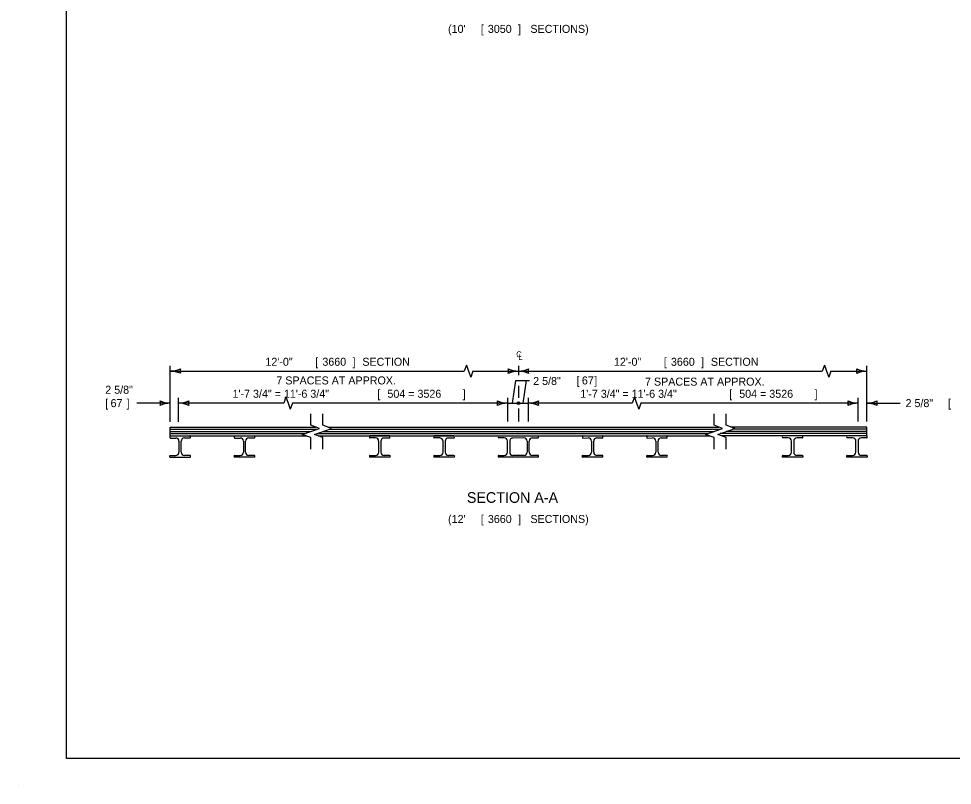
# Model space of a CAD drawing. Extents: x 49991.4 to 50021, y 49987.6 to 50011.4.
# Drawn here: x 49999.02 to 50006.02, y 49987.6 to 49993.35 of the extents above; entities that cross this region are included whole.
import ezdxf

# ---------------------------------------------------------------- set-up
doc = ezdxf.new("R2010")
doc.units = 0
for name, color, linetype in [('Level 1', 7, 'Continuous'), ('Level 10', 7, 'Continuous'), ('Level 2', 7, 'Continuous'), ('Level 3', 7, 'Continuous'), ('Level 6', 7, 'Continuous')]:
    doc.layers.add(name, color=color, linetype=linetype)

msp = doc.modelspace()

# ---------------------------------------------------------------- linework, layer by layer
at = {"layer": 'Level 1'}
for p, q in [((50000.1608, 49990.2845), (50001.2499, 49990.2846)), ((50000.1608, 49990.219), (50000.1608, 49990.2845)), ((50001.3411, 49990.2846), (50004.2726, 49990.2846)), ((50005.3818, 49990.2846), (50004.3638, 49990.2846)), ((50005.3818, 49990.219), (50005.3818, 49990.2846)), ((50000.1608, 49990.2682), (50001.2606, 49990.2682)), ((50000.1608, 49990.2518), (50001.2144, 49990.2518)), ((50000.1608, 49990.2355), (50001.1684, 49990.2355)), ((50000.1608, 49990.219), (50001.1789, 49990.219)), ((50000.1608, 49990.2184), (50000.3087, 49990.2186)), ((50000.6434, 49990.2184), (50000.7913, 49990.2186)), ((50001.2596, 49990.2355), (50004.1911, 49990.2355)), ((50001.2701, 49990.219), (50004.2016, 49990.219)), ((50001.3056, 49990.2518), (50004.2371, 49990.2518)), ((50001.3518, 49990.2682), (50004.2833, 49990.2682)), ((50001.8048, 49990.2183), (50001.657, 49990.2186)), ((50002.2874, 49990.2183), (50002.1396, 49990.2186)), ((50002.6221, 49990.2186), (50002.918, 49990.2187)), ((50003.2526, 49990.2185), (50003.4005, 49990.2187)), ((50003.7352, 49990.2185), (50003.8832, 49990.2187)), ((50005.3818, 49990.2355), (50004.2823, 49990.2355)), ((50005.3818, 49990.219), (50004.2928, 49990.219)), ((50005.3818, 49990.2518), (50004.3283, 49990.2518)), ((50005.3818, 49990.2682), (50004.3745, 49990.2682)), ((50004.8992, 49990.2186), (50004.7513, 49990.2188)), ((50005.3818, 49990.2186), (50005.2339, 49990.2188)), ((50000.1609, 49990.202), (50000.2015, 49990.2021)), ((50000.226, 49990.1776), (50000.226, 49990.096)), ((50000.2428, 49990.0962), (50000.2428, 49990.1777)), ((50000.2671, 49990.2022), (50000.3087, 49990.2023)), ((50000.6435, 49990.202), (50000.6841, 49990.2021)), ((50000.7086, 49990.1776), (50000.7086, 49990.096)), ((50000.7254, 49990.0962), (50000.7254, 49990.1777)), ((50000.7497, 49990.2022), (50000.7913, 49990.2023)), ((50001.6985, 49990.2022), (50001.6569, 49990.2022)), ((50001.7229, 49990.0962), (50001.7229, 49990.1777)), ((50001.7396, 49990.1776), (50001.7396, 49990.096)), ((50001.8048, 49990.202), (50001.7642, 49990.202)), ((50002.1811, 49990.2022), (50002.1396, 49990.2022)), ((50002.2055, 49990.0962), (50002.2055, 49990.1777)), ((50002.2222, 49990.1776), (50002.2222, 49990.096)), ((50002.2874, 49990.202), (50002.2468, 49990.202)), ((50002.6637, 49990.2022), (50002.6221, 49990.2022)), ((50002.6881, 49990.0962), (50002.6881, 49990.1777)), ((50002.7048, 49990.1776), (50002.7048, 49990.096)), ((50002.8107, 49990.2022), (50002.7294, 49990.202)), ((50002.8353, 49990.1777), (50002.8353, 49990.0961)), ((50002.852, 49990.0964), (50002.852, 49990.1778)), ((50002.8763, 49990.2023), (50002.918, 49990.2024)), ((50003.2527, 49990.2021), (50003.2933, 49990.2022)), ((50003.3178, 49990.1777), (50003.3178, 49990.0961)), ((50003.3346, 49990.0964), (50003.3346, 49990.1778)), ((50003.3589, 49990.2023), (50003.4005, 49990.2024)), ((50003.7353, 49990.2021), (50003.7759, 49990.2022)), ((50003.8004, 49990.1777), (50003.8004, 49990.0961)), ((50003.8172, 49990.0964), (50003.8172, 49990.1778)), ((50003.8415, 49990.2023), (50003.8832, 49990.2024)), ((50004.7929, 49990.2024), (50004.7513, 49990.2024)), ((50004.8172, 49990.0964), (50004.8172, 49990.1779)), ((50004.834, 49990.1778), (50004.834, 49990.0962)), ((50004.8992, 49990.2022), (50004.8586, 49990.2023)), ((50005.2755, 49990.2024), (50005.2339, 49990.2024)), ((50005.2998, 49990.0964), (50005.2998, 49990.1779)), ((50005.3166, 49990.1778), (50005.3166, 49990.0962)), ((50005.3818, 49990.2022), (50005.3412, 49990.2023)), ((50000.1612, 49990.0714), (50000.2016, 49990.0714)), ((50000.3087, 49990.0718), (50000.2674, 49990.0718)), ((50000.6438, 49990.0714), (50000.6842, 49990.0714)), ((50000.7913, 49990.0718), (50000.75, 49990.0718)), ((50001.6569, 49990.0718), (50001.6983, 49990.0718)), ((50001.8045, 49990.0713), (50001.7641, 49990.0714)), ((50002.1395, 49990.0718), (50002.1809, 49990.0718)), ((50002.2871, 49990.0713), (50002.2467, 49990.0714)), ((50002.6221, 49990.0718), (50002.6635, 49990.0718)), ((50002.8108, 49990.0716), (50002.7293, 49990.0714)), ((50002.918, 49990.0719), (50002.8766, 49990.0719)), ((50003.253, 49990.0715), (50003.2934, 49990.0716)), ((50003.4006, 49990.0719), (50003.3592, 49990.0719)), ((50003.7356, 49990.0715), (50003.776, 49990.0716)), ((50003.8832, 49990.0719), (50003.8418, 49990.0719)), ((50004.7513, 49990.072), (50004.7927, 49990.072)), ((50004.8989, 49990.0716), (50004.8584, 49990.0716)), ((50005.2339, 49990.072), (50005.2753, 49990.072)), ((50005.3815, 49990.0716), (50005.341, 49990.0716)), ((50000.1603, 49990.0576), (50000.3094, 49990.0576)), ((50000.792, 49990.0576), (50000.6429, 49990.0576)), ((50001.8055, 49990.0576), (50001.6562, 49990.0576)), ((50002.2881, 49990.0576), (50002.1388, 49990.0576)), ((50002.9185, 49990.0577), (50002.6213, 49990.0576)), ((50003.4011, 49990.0577), (50003.2523, 49990.0577)), ((50003.8838, 49990.0577), (50003.7348, 49990.0577)), ((50004.8999, 49990.0578), (50004.7506, 49990.0578)), ((50005.3828, 49990.0579), (50005.233, 49990.0579)), ((49999.0245, 49987.5988), (49999.0245, 49987.5988))]:
    msp.add_line(p, q, dxfattribs=at)
msp.add_lwpolyline([(49999.3835, 49998.9992), (50016.7501, 49998.9992), (50016.7501, 49987.7988), (49999.3835, 49987.7988)], close=True, dxfattribs=at)
for centre, radius, start, end in [((50001.7022, 49990.1815), 0.021, 349.58231, 100.06069), ((50000.2015, 49990.1776), 0.0245, 0.13085, 90.13085), ((50000.2676, 49990.1774), 0.0248, 91.12542, 179.23159), ((50000.6841, 49990.1776), 0.0245, 0.13085, 90.13085), ((50000.7475, 49990.1801), 0.0222, 84.14406, 186.21295), ((50001.7641, 49990.1775), 0.0245, 89.86915, 179.86915), ((50002.1778, 49990.1745), 0.0279, 6.54158, 83.10142), ((50002.2467, 49990.1775), 0.0245, 89.86915, 179.86915), ((50002.6657, 49990.1798), 0.0225, 354.61543, 95.02756), ((50002.7293, 49990.1775), 0.0245, 89.86915, 179.86915), ((50002.8108, 49990.1777), 0.0245, 0.13085, 90.13085), ((50002.874, 49990.1803), 0.0222, 83.95297, 186.40404), ((50003.2933, 49990.1777), 0.0245, 0.13085, 90.13085), ((50003.3583, 49990.1787), 0.0237, 88.32603, 182.03098), ((50003.7759, 49990.1777), 0.0245, 0.13085, 90.13085), ((50003.8403, 49990.1792), 0.0232, 87.00728, 183.34973), ((50004.7928, 49990.178), 0.0244, 359.87659, 89.76641), ((50004.8579, 49990.1784), 0.0239, 88.36941, 181.3689), ((50005.2767, 49990.1792), 0.0232, 356.71012, 92.93287), ((50005.3396, 49990.1793), 0.023, 86.11132, 183.62699), ((50000.2015, 49990.0959), 0.0245, 270.13085, 0.13085), ((50000.2673, 49990.0963), 0.0245, 180.13085, 270.13085), ((50000.6841, 49990.0959), 0.0245, 270.13085, 0.13085), ((50000.7499, 49990.0963), 0.0245, 180.13085, 270.13085), ((50001.6984, 49990.0963), 0.0245, 269.86915, 359.86915), ((50001.7641, 49990.0959), 0.0245, 179.86915, 269.86915), ((50002.181, 49990.0963), 0.0245, 269.86915, 359.86915), ((50002.2467, 49990.0959), 0.0245, 179.86915, 269.86915), ((50002.6636, 49990.0963), 0.0245, 269.86915, 359.86915), ((50002.7293, 49990.0959), 0.0245, 179.86915, 269.86915), ((50002.8108, 49990.0961), 0.0245, 270.13085, 0.13085), ((50002.8765, 49990.0964), 0.0245, 180.13085, 270.13085), ((50003.2933, 49990.0961), 0.0245, 270.13085, 0.13085), ((50003.3591, 49990.0964), 0.0245, 180.13085, 270.13085), ((50003.7759, 49990.0961), 0.0245, 270.13085, 0.13085), ((50003.8417, 49990.0964), 0.0245, 180.13085, 270.13085), ((50004.7927, 49990.0965), 0.0245, 269.86915, 359.86915), ((50004.8585, 49990.0961), 0.0245, 179.86915, 269.86915), ((50005.2753, 49990.0965), 0.0245, 269.86915, 359.86915), ((50005.3411, 49990.0961), 0.0245, 179.86915, 269.86915)]:
    msp.add_arc(centre, radius, start, end, dxfattribs=at)
for centre, major_axis, ratio, start_param, end_param in [((50000.1609, 49990.2102), (-0.00002, 0.00817), 0.356754, 0, 3.141593), ((50000.3087, 49990.2104), (0.00002, -0.00817), 0.392805, 0, 3.141593), ((50000.6435, 49990.2102), (-0.00002, 0.00817), 0.356754, 0, 3.141593), ((50000.7913, 49990.2104), (0.00002, -0.00817), 0.392805, 0, 3.141593), ((50001.657, 49990.2104), (-0.00002, -0.00817), 0.392805, 3.141593, 6.283185), ((50001.8048, 49990.2102), (0.00002, 0.00817), 0.356754, 3.141593, 6.283185), ((50002.1396, 49990.2104), (-0.00002, -0.00817), 0.392805, 3.141593, 6.283185), ((50002.2874, 49990.2102), (0.00002, 0.00817), 0.356754, 3.141593, 6.283185), ((50002.6222, 49990.2104), (-0.00002, -0.00817), 0.392805, 3.141593, 6.283185), ((50002.9179, 49990.2105), (0.00002, -0.00817), 0.392805, 0, 3.141593), ((50003.2527, 49990.2103), (-0.00002, 0.00817), 0.356754, 0, 3.141593), ((50003.4005, 49990.2105), (0.00002, -0.00817), 0.392805, 0, 3.141593), ((50003.7353, 49990.2103), (-0.00002, 0.00817), 0.356754, 0, 3.141593), ((50003.8831, 49990.2105), (0.00002, -0.00817), 0.392805, 0, 3.141593), ((50004.7513, 49990.2106), (-0.00002, -0.00817), 0.392805, 3.141593, 6.283185), ((50004.8992, 49990.2104), (0.00002, 0.00817), 0.356754, 3.141593, 6.283185), ((50005.2339, 49990.2106), (-0.00002, -0.00817), 0.392805, 3.141593, 6.283185), ((50005.3818, 49990.2104), (0.00002, 0.00817), 0.356754, 3.141593, 6.283185), ((50000.1614, 49990.0644), (-0.00025, 0.00695), 0.928868, 0, 2.919512), ((50000.3087, 49990.0646), (-0.00003, -0.00717), 0.534325, 0.187696, 3.141593), ((50000.644, 49990.0644), (-0.00025, 0.00695), 0.928868, 0, 2.919512), ((50000.7913, 49990.0646), (-0.00003, -0.00717), 0.534325, 0.187696, 3.141593), ((50001.657, 49990.0646), (0.00003, -0.00717), 0.534325, 3.141593, 6.076715), ((50001.8042, 49990.0644), (0.00025, 0.00695), 0.928868, 3.382741, 6.283185), ((50002.1396, 49990.0646), (0.00003, -0.00717), 0.534325, 3.141593, 6.076713), ((50002.2868, 49990.0644), (0.00025, 0.00695), 0.928868, 3.382741, 6.283185), ((50002.6222, 49990.0646), (0.00003, -0.00717), 0.534325, 3.141593, 6.043934), ((50002.9179, 49990.0647), (-0.00003, -0.00717), 0.534325, 0.146109, 3.141593), ((50003.2532, 49990.0645), (-0.00025, 0.00695), 0.928868, 0, 2.951883), ((50003.4005, 49990.0647), (-0.00003, -0.00717), 0.534325, 0.161043, 3.141593), ((50003.7358, 49990.0645), (-0.00025, 0.00695), 0.928868, 0, 2.93527), ((50003.8831, 49990.0647), (-0.00003, -0.00717), 0.534325, 0.176923, 3.141593), ((50004.7513, 49990.0648), (0.00003, -0.00717), 0.534325, 3.141593, 6.095489), ((50004.8986, 49990.0646), (0.00025, 0.00695), 0.928868, 3.382741, 6.283185), ((50005.2339, 49990.0648), (0.00003, -0.00717), 0.534325, 3.141593, 6.039934), ((50005.3812, 49990.0646), (0.00025, 0.00695), 0.928868, 3.435164, 6.283185)]:
    msp.add_ellipse(centre, major_axis=major_axis, ratio=ratio, start_param=start_param, end_param=end_param, dxfattribs=at)
at = {"layer": 'Level 10'}
msp.add_line((50002.7702, 49990.7434), (50002.7702, 49990.7434), dxfattribs=at)
at = {"layer": 'Level 3'}
for p, q in [((50000.1608, 49990.3245), (50000.1608, 49990.7437)), ((50000.1608, 49990.7037), (50001.9664, 49990.7034)), ((50001.9664, 49990.7034), (50002.364, 49990.7034)), ((50002.3802, 49990.749), (50002.364, 49990.7034)), ((50002.3802, 49990.749), (50002.3964, 49990.7034)), ((50002.3964, 49990.7034), (50002.4126, 49990.6576)), ((50002.4288, 49990.7034), (50002.4126, 49990.6576)), ((50002.4288, 49990.7034), (50002.7702, 49990.7034)), ((50002.7702, 49990.7434), (50002.7702, 49990.6734)), ((50002.7702, 49990.7034), (50004.5789, 49990.7031)), ((50004.5789, 49990.7031), (50005.0481, 49990.7031)), ((50005.0643, 49990.7487), (50005.0481, 49990.7031)), ((50005.0643, 49990.7487), (50005.0805, 49990.7031)), ((50005.0805, 49990.7031), (50005.0967, 49990.6573)), ((50005.1129, 49990.7031), (50005.0967, 49990.6573)), ((50005.1129, 49990.7031), (50005.3819, 49990.7031)), ((50005.3819, 49990.3246), (50005.3819, 49990.7431)), ((50002.7256, 49990.4636), (50002.7506, 49990.6334)), ((50002.7506, 49990.6334), (50002.8534, 49990.6334)), ((50002.807, 49990.4635), (50002.832, 49990.6334)), ((50002.7702, 49990.5934), (50002.7702, 49990.5035)), ((50000.2232, 49990.3245), (50000.2232, 49990.5037)), ((50001.0278, 49990.5095), (50001.0116, 49990.4637)), ((50001.0278, 49990.5095), (50001.044, 49990.4637)), ((50002.6886, 49990.5037), (50002.6886, 49990.3246)), ((50002.8442, 49990.5034), (50002.8442, 49990.3246)), ((50003.6403, 49990.5092), (50003.6241, 49990.4634)), ((50003.6403, 49990.5092), (50003.6565, 49990.4634)), ((50005.3171, 49990.3246), (50005.3171, 49990.5034)), ((50000.1608, 49990.4637), (49999.9106, 49990.4637)), ((50001.0116, 49990.4637), (50000.2232, 49990.4637)), ((50001.044, 49990.4637), (50001.0602, 49990.4181)), ((50001.0764, 49990.4637), (50001.0602, 49990.4181)), ((50002.6886, 49990.4637), (50001.0764, 49990.4637)), ((50002.6886, 49990.4637), (50002.8442, 49990.4634)), ((50002.7702, 49990.4235), (50002.7702, 49990.3246)), ((50003.6241, 49990.4634), (50002.8442, 49990.4634)), ((50003.6565, 49990.4634), (50003.6727, 49990.4178)), ((50003.6889, 49990.4634), (50003.6727, 49990.4178)), ((50005.3171, 49990.4634), (50003.6889, 49990.4634)), ((50005.3819, 49990.4637), (50005.6321, 49990.4637))]:
    msp.add_line(p, q, dxfattribs=at)
msp.add_circle((50002.771, 49990.4631), 0.01, dxfattribs=at)
for centre, radius, start, end in [((50000.1493, 49990.9364), 0.233, 272.82731, 292.07716), ((50000.1517, 49990.4816), 0.2223, 67.45601, 87.63952), ((50000.2891, 49990.7037), 0.0548, 162.13882, 197.86118), ((50002.7794, 49990.9255), 0.2223, 247.45601, 267.63952), ((50002.642, 49990.7034), 0.0548, 342.13882, 17.86118), ((50002.7817, 49990.4707), 0.233, 92.82731, 112.07716), ((50002.7588, 49990.9361), 0.233, 272.82731, 292.07716), ((50002.7611, 49990.4813), 0.2223, 67.45601, 87.63952), ((50002.8985, 49990.7034), 0.0548, 162.13882, 197.86118), ((50005.3911, 49990.9253), 0.2223, 247.45601, 267.63952), ((50005.2537, 49990.7031), 0.0548, 342.13882, 17.86118), ((50005.3934, 49990.4704), 0.233, 92.82731, 112.07716), ((50000.17, 49990.6858), 0.2223, 247.45601, 267.63952), ((50000.0326, 49990.4637), 0.0548, 342.13882, 17.86118), ((50000.1723, 49990.231), 0.233, 92.82731, 112.07716), ((50000.2118, 49990.6964), 0.233, 272.82731, 292.07716), ((50000.2141, 49990.2416), 0.2223, 67.45601, 87.63952), ((50000.3515, 49990.4637), 0.0548, 162.13882, 197.86118), ((50002.6978, 49990.6858), 0.2223, 247.45601, 267.63952), ((50002.5604, 49990.4637), 0.0548, 342.13882, 17.86118), ((50002.7001, 49990.231), 0.233, 92.82731, 112.07716), ((50002.8327, 49990.6961), 0.233, 272.82731, 292.07716), ((50002.835, 49990.2413), 0.2223, 67.45601, 87.63952), ((50002.9724, 49990.4634), 0.0548, 162.13882, 197.86118), ((50005.3263, 49990.6855), 0.2223, 247.45601, 267.63952), ((50005.1889, 49990.4634), 0.0548, 342.13882, 17.86118), ((50005.3286, 49990.2307), 0.233, 92.82731, 112.07716), ((50005.3704, 49990.6964), 0.233, 272.82731, 292.07716), ((50005.3727, 49990.2416), 0.2223, 67.45601, 87.63952), ((50005.5101, 49990.4637), 0.0548, 162.13882, 197.86118)]:
    msp.add_arc(centre, radius, start, end, dxfattribs=at)
at = {"layer": 'Level 6'}
for points in [[(50001.2144, 49990.1193), (50001.2144, 49990.2064), (50001.1504, 49990.2291), (50001.2784, 49990.2745), (50001.2144, 49990.2972), (50001.2144, 49990.3843)], [(50001.3056, 49990.1193), (50001.3056, 49990.2064), (50001.2416, 49990.2291), (50001.3696, 49990.2745), (50001.3056, 49990.2972), (50001.3056, 49990.3843)], [(50004.2371, 49990.1193), (50004.2371, 49990.2064), (50004.1731, 49990.2291), (50004.3011, 49990.2745), (50004.2371, 49990.2972), (50004.2371, 49990.3843)], [(50004.3283, 49990.1193), (50004.3283, 49990.2064), (50004.2643, 49990.2291), (50004.3923, 49990.2745), (50004.3283, 49990.2972), (50004.3283, 49990.3843)]]:
    msp.add_lwpolyline(points, dxfattribs=at)

# ---------------------------------------------------------------- texts
at = {"layer": 'Level 10'}
for s, p in [('C', (50002.7541, 49990.8081)), ('L', (50002.7705, 49990.7868))]:
    msp.add_text(s, height=0.0432, dxfattribs=at).set_placement(p)
at = {"layer": 'Level 2'}
for s, height, p in [("(10' ", 0.06, (50002.243, 49993.2386)), ('[', 0.06, (50002.4881, 49993.2386)), ('3050', 0.06, (50002.5414, 49993.2386)), (']', 0.06, (50002.7678, 49993.2386)), (' SECTIONS)', 0.06, (50002.8378, 49993.2386)), ('12\'-0" ', 0.06, (50000.8739, 49990.7435)), ('[', 0.06, (50001.2476, 49990.7435)), ('3660', 0.06, (50001.3009, 49990.7435)), (']', 0.06, (50001.5273, 49990.7435)), (' SECTION', 0.06, (50001.5781, 49990.7435)), ('12\'-0" ', 0.06, (50003.4866, 49990.7433)), ('[', 0.06, (50003.8603, 49990.7433)), ('3660', 0.06, (50003.9136, 49990.7433)), (']', 0.06, (50004.14, 49990.7433)), (' SECTION', 0.06, (50004.1908, 49990.7433)), ('7 SPACES AT APPROX.', 0.06, (50000.9561, 49990.6037)), ('2 5/8" ', 0.06, (50002.881, 49990.5996)), ('[', 0.06, (50003.2065, 49990.6034)), ('67', 0.06, (50003.2462, 49990.6034)), (']', 0.06, (50003.3386, 49990.6038)), ('7 SPACES AT APPROX.', 0.06, (50003.7193, 49990.5946)), ('2 5/8"', 0.06, (49999.6736, 49990.5337)), ('1\'-7 3/4" = 11\'-6 3/4" ', 0.06, (50000.6274, 49990.5037)), ('[', 0.06, (50001.7132, 49990.5037)), ('504 = 3526', 0.06, (50001.7885, 49990.5037)), (']', 0.06, (50002.3529, 49990.5037)), ('1\'-7 3/4" = 11\'-6 3/4" ', 0.06, (50003.2341, 49990.5034)), ('[', 0.06, (50004.3503, 49990.5034)), ('504 = 3526', 0.06, (50004.4256, 49990.5034)), (']', 0.06, (50004.99, 49990.5034)), ('[', 0.06, (49999.6736, 49990.4337)), ('67', 0.06, (49999.7133, 49990.4337)), (']', 0.06, (49999.8333, 49990.4337)), ('2 5/8" ', 0.06, (50005.6721, 49990.4337)), ('[', 0.06, (50005.9901, 49990.4337)), ('SECTION A-A', 0.08, (50002.3842, 49989.7161)), ("(12' ", 0.06, (50002.2431, 49989.5651)), ('[', 0.06, (50002.4882, 49989.5651)), ('3660', 0.06, (50002.5415, 49989.5651)), (']', 0.06, (50002.7679, 49989.5651)), (' SECTIONS)', 0.06, (50002.8379, 49989.5651))]:
    msp.add_text(s, height=height, dxfattribs=at).set_placement(p)

doc.saveas('drawing.dxf')
